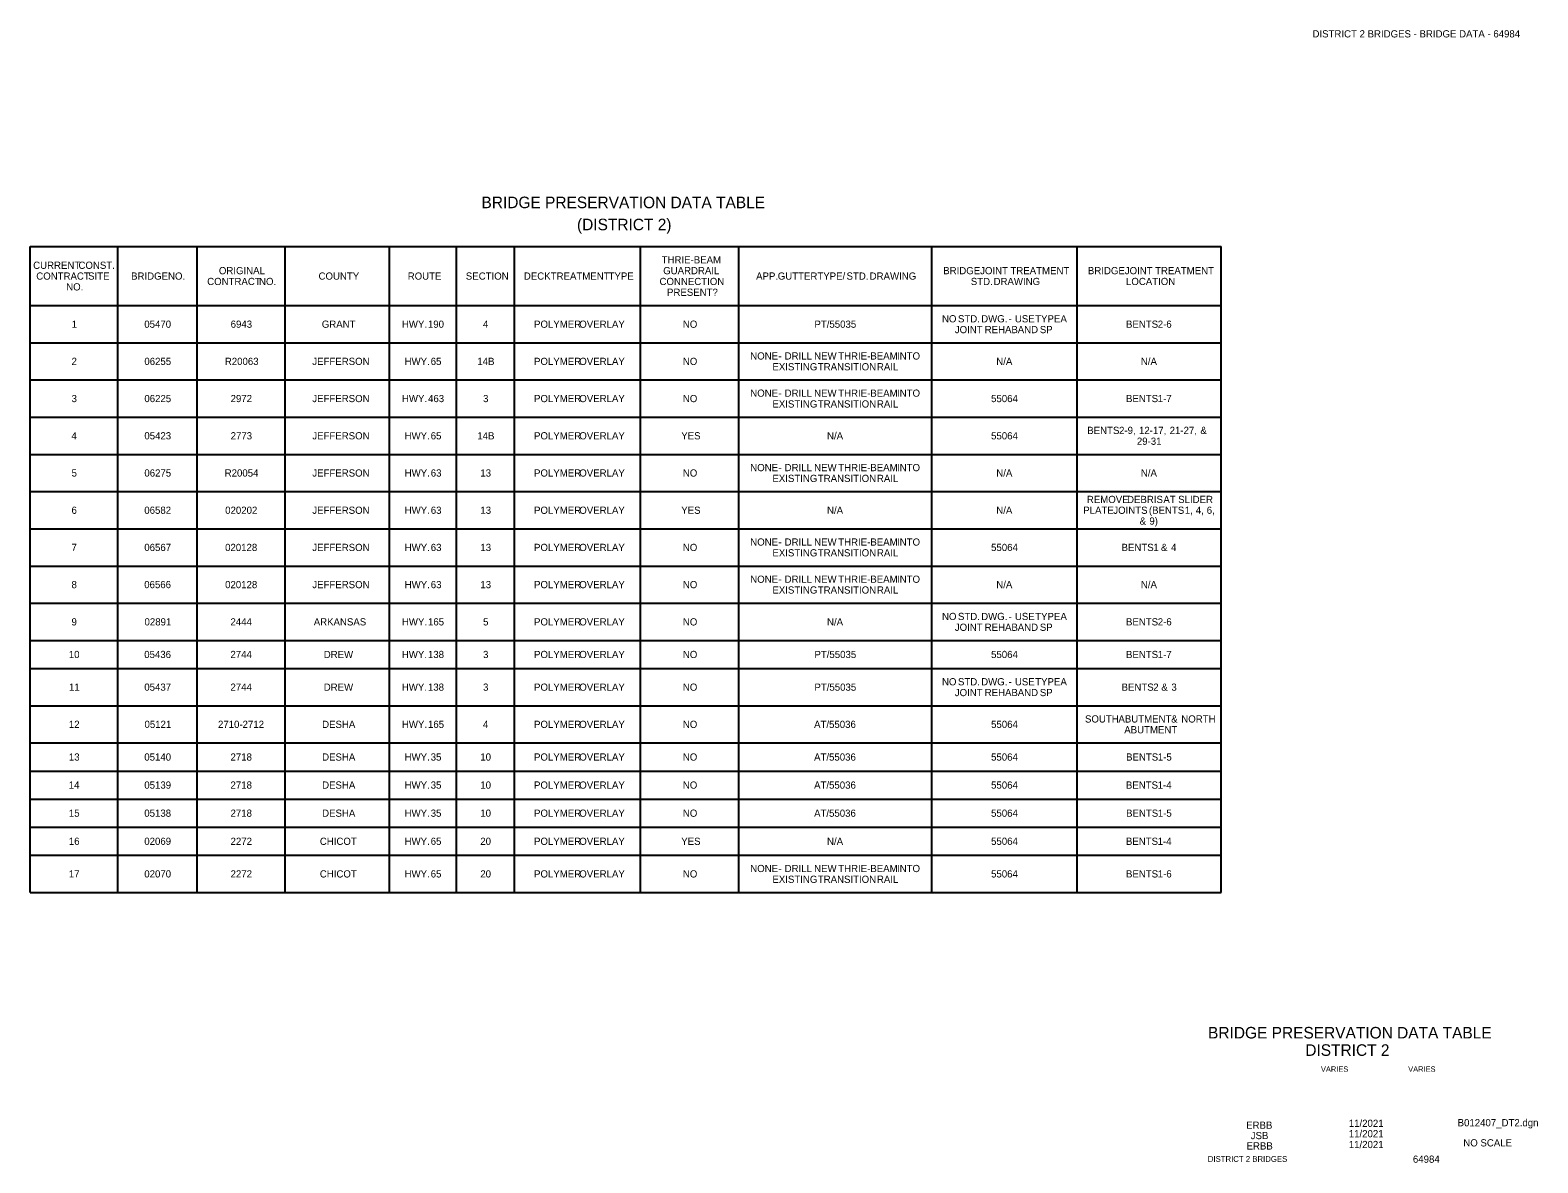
# Model space of a CAD drawing. Extents: x 16 to 1228740, y 11 to 152440.
import ezdxf

# ---------------------------------------------------------------- set-up
doc = ezdxf.new("R2010")
doc.units = 0
for name, color, linetype in [('B_border', 7, 'Continuous'), ('B_Concrete hidden', 7, 'Continuous'), ('Default', 7, 'Continuous')]:
    doc.layers.add(name, color=color, linetype=linetype)

msp = doc.modelspace()

# ---------------------------------------------------------------- linework, layer by layer
at = {"layer": 'B_border'}
msp.add_line((16.2529, 12.0926), (16.2529, 12.0926), dxfattribs=at)
at = {"layer": 'Default'}
for p, q in [((16.2529, 12.0926), (17.9726, 12.0926)), ((16.2529, 11.1597), (16.2529, 12.0926)), ((16.3796, 11.1597), (16.3796, 12.0926)), ((16.4942, 11.1597), (16.4942, 12.0926)), ((16.6209, 11.1597), (16.6209, 12.0926)), ((16.772, 11.1597), (16.772, 12.0926)), ((16.8684, 11.1597), (16.8684, 12.0926)), ((16.9525, 11.1597), (16.9525, 12.0926)), ((17.134, 11.1597), (17.134, 12.0926)), ((17.276, 11.1597), (17.276, 12.0926)), ((17.5548, 11.1597), (17.5548, 12.0926)), ((17.7647, 11.1597), (17.7647, 12.0926)), ((17.9726, 11.1597), (17.9726, 12.0926)), ((16.2529, 12.0074), (17.9726, 12.0074)), ((16.2529, 11.9537), (17.9726, 11.9537)), ((16.2529, 11.8999), (17.9726, 11.8999)), ((16.2529, 11.8462), (17.9726, 11.8462)), ((16.2529, 11.7924), (17.9726, 11.7924)), ((16.2529, 11.7387), (17.9726, 11.7387)), ((16.2529, 11.685), (17.9726, 11.685)), ((16.2529, 11.6312), (17.9726, 11.6312)), ((16.2529, 11.5775), (17.9726, 11.5775)), ((16.2529, 11.5237), (17.9726, 11.5237)), ((16.2529, 11.4832), (17.9726, 11.4832)), ((16.2529, 11.4294), (17.9726, 11.4294)), ((16.2529, 11.3757), (17.9726, 11.3757)), ((16.2529, 11.3351), (17.9726, 11.3351)), ((16.2529, 11.2946), (17.9726, 11.2946)), ((16.2529, 11.254), (17.9726, 11.254)), ((16.2529, 11.2135), (17.9726, 11.2135)), ((16.2529, 11.1597), (17.9726, 11.1597))]:
    msp.add_line(p, q, dxfattribs=at)

# ---------------------------------------------------------------- texts
at = {"layer": 'B_border'}
for s, p in [('BRIDGE PRESERVATION DATA TABLE ', (16.9046, 12.148)), ('(DISTRICT 2)', (17.0425, 12.1161))]:
    msp.add_text(s, height=0.0167, rotation=360, dxfattribs=at).set_placement(p)
at = {"layer": 'B_Concrete hidden'}
for s, height, p in [('DISTRICT 2 BRIDGES - BRIDGE DATA - 64984', 0.0104, (18.1046, 12.3946)), ('BRIDGE PRESERVATION DATA TABLE', 0.0167, (17.9538, 10.9489)), ('DISTRICT 2', 0.0167, (18.0942, 10.9238)), ('VARIES', 0.0078, (18.1168, 10.9008)), ('VARIES', 0.0078, (18.2428, 10.9008)), ('ERBB', 0.0104, (18.0088, 10.8185)), ('11/2021', 0.0104, (18.157, 10.8212)), ('B012407_DT2.dgn', 0.0104, (18.3142, 10.8221)), ('ERBB', 0.0104, (18.0094, 10.7885)), ('JSB', 0.0104, (18.0154, 10.8035)), ('11/2021', 0.0104, (18.157, 10.8062)), ('11/2021', 0.0104, (18.157, 10.7906)), ('NO SCALE', 0.0104, (18.3224, 10.793)), ('DISTRICT 2 BRIDGES', 0.0084, (17.9534, 10.7707)), ('64984', 0.01042, (18.2496, 10.7694))]:
    msp.add_text(s, height=height, dxfattribs=at).set_placement(p)
at = {"layer": 'Default'}
for s, p in [('CURRENT', (16.2572, 12.0604)), (' CONST.', (16.3188, 12.0604)), ('ORIGINAL', (16.5254, 12.0526)), ('THRIE-BEAM', (17.1648, 12.0682)), ('GUARDRAIL', (17.167, 12.0526)), ('BRIDGE', (17.5714, 12.0526)), (' JOINT', (17.6208, 12.0526)), (' TREATMENT', (17.6646, 12.0526)), ('BRIDGE', (17.7803, 12.0526)), (' JOINT', (17.8297, 12.0526)), (' TREATMENT', (17.8735, 12.0526)), ('CONTRACT', (16.2617, 12.0448)), ('NO.', (16.3049, 12.0292)), (' SITE', (16.3327, 12.0448)), ('BRIDGE', (16.3986, 12.0448)), (' NO.', (16.4481, 12.0448)), ('CONTRACT', (16.5085, 12.037)), (' NO.', (16.5795, 12.037)), ('COUNTY', (16.6693, 12.0448)), ('ROUTE', (16.7981, 12.0448)), ('SECTION', (16.882, 12.0448)), ('DECK', (16.9658, 12.0448)), (' TREATMENT', (17.0007, 12.0448)), (' TYPE', (17.0843, 12.0448)), ('CONNECTION', (17.1617, 12.037)), ('APP.', (17.3012, 12.0448)), (' GUTTER', (17.3286, 12.0448)), (' TYPE/', (17.3858, 12.0448)), (' STD.', (17.4279, 12.0448)), (' DRAWING', (17.4613, 12.0448)), ('STD.', (17.6112, 12.037)), (' DRAWING', (17.6402, 12.037)), ('LOCATION', (17.8353, 12.037)), ('PRESENT?', (17.1725, 12.0214)), ('1', (16.3129, 11.9753)), ('05470', (16.4177, 11.9753)), ('6943', (16.5424, 11.9753)), ('GRANT', (16.674, 11.9753)), ('HWY.', (16.7897, 11.9753)), (' 190', (16.8234, 11.9753)), ('4', (16.9067, 11.9753)), ('POLYMER', (16.9805, 11.9753)), (' OVERLAY', (17.042, 11.9753)), ('NO', (17.1954, 11.9753)), ('PT/55035', (17.3854, 11.9753)), ('NO', (17.5696, 11.9831)), ('JOINT', (17.5881, 11.9675)), (' STD.', (17.5888, 11.9831)), (' DWG.', (17.6223, 11.9831)), (' REHAB', (17.6274, 11.9675)), (' -', (17.6619, 11.9831)), (' USE', (17.671, 11.9831)), (' AND', (17.6751, 11.9675)), (' TYPE', (17.7003, 11.9831)), (' SP', (17.707, 11.9675)), (' A', (17.7368, 11.9831)), ('BENTS', (17.8353, 11.9753)), (' 2-6', (17.8773, 11.9753)), ('2', (16.3127, 11.9216)), ('06255', (16.4178, 11.9216)), ('R20063', (16.534, 11.9216)), ('JEFFERSON', (16.6603, 11.9216)), ('HWY.', (16.7936, 11.9216)), (' 65', (16.8274, 11.9216)), ('14B', (16.8986, 11.9216)), ('POLYMER', (16.9805, 11.9216)), (' OVERLAY', (17.042, 11.9216)), ('NO', (17.1954, 11.9216)), ('NONE', (17.2927, 11.9294)), (' -', (17.3295, 11.9294)), (' DRILL', (17.3385, 11.9294)), (' NEW', (17.3811, 11.9294)), (' THRIE-BEAM', (17.4159, 11.9294)), (' INTO', (17.5008, 11.9294)), ('N/A', (17.648, 11.9216)), ('N/A', (17.8568, 11.9216)), ('EXISTING', (17.3247, 11.9138)), (' TRANSITION', (17.3864, 11.9138)), (' RAIL', (17.4718, 11.9138)), ('3', (16.3127, 11.8679)), ('06225', (16.4178, 11.8679)), ('2972', (16.5423, 11.8679)), ('JEFFERSON', (16.6603, 11.8679)), ('HWY.', (16.7898, 11.8679)), (' 463', (16.8236, 11.8679)), ('3', (16.9069, 11.8679)), ('POLYMER', (16.9805, 11.8679)), (' OVERLAY', (17.042, 11.8679)), ('NO', (17.1954, 11.8679)), ('NONE', (17.2927, 11.8757)), ('EXISTING', (17.3247, 11.8601)), (' -', (17.3295, 11.8757)), (' DRILL', (17.3385, 11.8757)), (' NEW', (17.3811, 11.8757)), (' TRANSITION', (17.3864, 11.8601)), (' THRIE-BEAM', (17.4159, 11.8757)), (' RAIL', (17.4718, 11.8601)), (' INTO', (17.5008, 11.8757)), ('55064', (17.6405, 11.8679)), ('BENTS', (17.8353, 11.8679)), (' 1-7', (17.8773, 11.8679)), ('4', (16.3125, 11.8141)), ('05423', (16.4178, 11.8141)), ('2773', (16.5424, 11.8141)), ('JEFFERSON', (16.6603, 11.8141)), ('HWY.', (16.7936, 11.8141)), (' 65', (16.8274, 11.8141)), ('14B', (16.8986, 11.8141)), ('POLYMER', (16.9805, 11.8141)), (' OVERLAY', (17.042, 11.8141)), ('YES', (17.1931, 11.8141)), ('N/A', (17.4036, 11.8141)), ('55064', (17.6405, 11.8141)), ('BENTS', (17.7794, 11.8219)), (' 2-9,', (17.8214, 11.8219)), (' 12-17,', (17.8502, 11.8219)), (' 21-27,', (17.8945, 11.8219)), (' &', (17.9389, 11.8219)), ('29-31', (17.851, 11.8063)), ('NONE', (17.2927, 11.7682)), (' DRILL', (17.3385, 11.7682)), (' NEW', (17.3811, 11.7682)), (' THRIE-BEAM', (17.4159, 11.7682)), (' INTO', (17.5008, 11.7682)), ('5', (16.3127, 11.7604)), ('06275', (16.4178, 11.7604)), ('R20054', (16.5338, 11.7604)), ('JEFFERSON', (16.6603, 11.7604)), ('HWY.', (16.7937, 11.7604)), (' 63', (16.8275, 11.7604)), ('13', (16.903, 11.7604)), ('POLYMER', (16.9805, 11.7604)), (' OVERLAY', (17.042, 11.7604)), ('NO', (17.1954, 11.7604)), ('EXISTING', (17.3247, 11.7526)), (' -', (17.3295, 11.7682)), (' TRANSITION', (17.3864, 11.7526)), (' RAIL', (17.4718, 11.7526)), ('N/A', (17.648, 11.7604)), ('N/A', (17.8568, 11.7604)), ('6', (16.3126, 11.7066)), ('06582', (16.4177, 11.7066)), ('020202', (16.5345, 11.7066)), ('JEFFERSON', (16.6603, 11.7066)), ('HWY.', (16.7937, 11.7066)), (' 63', (16.8275, 11.7066)), ('13', (16.903, 11.7066)), ('POLYMER', (16.9805, 11.7066)), (' OVERLAY', (17.042, 11.7066)), ('YES', (17.1931, 11.7066)), ('N/A', (17.4036, 11.7066)), ('N/A', (17.648, 11.7066)), ('PLATE', (17.7736, 11.7066)), ('REMOVE', (17.7788, 11.7222)), (' JOINTS', (17.8131, 11.7066)), (' DEBRIS', (17.833, 11.7222)), (' (BENTS', (17.8645, 11.7066)), (' AT', (17.8854, 11.7222)), (' SLIDER', (17.9068, 11.7222)), (' 1,', (17.9164, 11.7066)), (' 4,', (17.9322, 11.7066)), (' 6,', (17.948, 11.7066)), ('&', (17.8551, 11.691)), (' 9)', (17.8652, 11.691)), ('NONE', (17.2927, 11.6607)), (' DRILL', (17.3385, 11.6607)), (' NEW', (17.3811, 11.6607)), (' THRIE-BEAM', (17.4159, 11.6607)), (' INTO', (17.5008, 11.6607)), ('7', (16.3126, 11.6529)), ('06567', (16.4177, 11.6529)), ('020128', (16.5344, 11.6529)), ('JEFFERSON', (16.6603, 11.6529)), ('HWY.', (16.7937, 11.6529)), (' 63', (16.8275, 11.6529)), ('13', (16.903, 11.6529)), ('POLYMER', (16.9805, 11.6529)), (' OVERLAY', (17.042, 11.6529)), ('NO', (17.1954, 11.6529)), ('EXISTING', (17.3247, 11.6451)), (' -', (17.3295, 11.6607)), (' TRANSITION', (17.3864, 11.6451)), (' RAIL', (17.4718, 11.6451)), ('55064', (17.6405, 11.6529)), ('BENTS', (17.8289, 11.6529)), (' 1', (17.8709, 11.6529)), (' &', (17.882, 11.6529)), (' 4', (17.8965, 11.6529)), ('8', (16.3126, 11.5992)), ('06566', (16.4176, 11.5992)), ('020128', (16.5344, 11.5992)), ('JEFFERSON', (16.6603, 11.5992)), ('HWY.', (16.7937, 11.5992)), (' 63', (16.8275, 11.5992)), ('13', (16.903, 11.5992)), ('POLYMER', (16.9805, 11.5992)), (' OVERLAY', (17.042, 11.5992)), ('NO', (17.1954, 11.5992)), ('NONE', (17.2927, 11.607)), (' -', (17.3295, 11.607)), (' DRILL', (17.3385, 11.607)), (' NEW', (17.3811, 11.607)), (' THRIE-BEAM', (17.4159, 11.607)), (' INTO', (17.5008, 11.607)), ('N/A', (17.648, 11.5992)), ('N/A', (17.8568, 11.5992)), ('EXISTING', (17.3247, 11.5914)), (' TRANSITION', (17.3864, 11.5914)), (' RAIL', (17.4718, 11.5914)), ('NO', (17.5696, 11.5532)), (' STD.', (17.5888, 11.5532)), (' DWG.', (17.6223, 11.5532)), (' USE', (17.671, 11.5532)), (' TYPE', (17.7003, 11.5532)), (' A', (17.7368, 11.5532)), ('9', (16.3126, 11.5454)), ('02891', (16.418, 11.5454)), ('2444', (16.5421, 11.5454)), ('ARKANSAS', (16.6624, 11.5454)), ('HWY.', (16.7897, 11.5454)), (' 165', (16.8235, 11.5454)), ('5', (16.9069, 11.5454)), ('POLYMER', (16.9805, 11.5454)), (' OVERLAY', (17.042, 11.5454)), ('NO', (17.1954, 11.5454)), ('N/A', (17.4036, 11.5454)), ('JOINT', (17.5881, 11.5376)), (' REHAB', (17.6274, 11.5376)), (' -', (17.6619, 11.5532)), (' AND', (17.6751, 11.5376)), (' SP', (17.707, 11.5376)), ('BENTS', (17.8353, 11.5454)), (' 2-6', (17.8773, 11.5454)), ('10', (16.3087, 11.4983)), ('05436', (16.4176, 11.4983)), ('2744', (16.5421, 11.4983)), ('DREW', (16.6768, 11.4983)), ('HWY.', (16.7896, 11.4983)), (' 138', (16.8234, 11.4983)), ('3', (16.9069, 11.4983)), ('POLYMER', (16.9805, 11.4983)), (' OVERLAY', (17.042, 11.4983)), ('NO', (17.1954, 11.4983)), ('PT/55035', (17.3854, 11.4983)), ('55064', (17.6405, 11.4983)), ('BENTS', (17.8353, 11.4983)), (' 1-7', (17.8773, 11.4983)), ('11', (16.309, 11.4511)), ('05437', (16.4177, 11.4511)), ('2744', (16.5421, 11.4511)), ('DREW', (16.6768, 11.4511)), ('HWY.', (16.7896, 11.4511)), (' 138', (16.8234, 11.4511)), ('3', (16.9069, 11.4511)), ('POLYMER', (16.9805, 11.4511)), (' OVERLAY', (17.042, 11.4511)), ('NO', (17.1954, 11.4511)), ('PT/55035', (17.3854, 11.4511)), ('NO', (17.5696, 11.4589)), ('JOINT', (17.5881, 11.4433)), (' STD.', (17.5888, 11.4589)), (' DWG.', (17.6223, 11.4589)), (' REHAB', (17.6274, 11.4433)), (' -', (17.6619, 11.4589)), (' USE', (17.671, 11.4589)), (' AND', (17.6751, 11.4433)), (' TYPE', (17.7003, 11.4589)), (' SP', (17.707, 11.4433)), (' A', (17.7368, 11.4589)), ('BENTS', (17.8289, 11.4511)), (' 2', (17.8708, 11.4511)), (' &', (17.8825, 11.4511)), (' 3', (17.897, 11.4511)), ('AT/55036', (17.3849, 11.3974)), ('SOUTH', (17.7761, 11.4052)), (' ABUTMENT', (17.8205, 11.4052)), (' &', (17.8967, 11.4052)), (' NORTH', (17.9113, 11.4052)), ('12', (16.3088, 11.3974)), ('05121', (16.418, 11.3974)), ('2710-2712', (16.5241, 11.3974)), ('DESHA', (16.6745, 11.3974)), ('HWY.', (16.7897, 11.3974)), (' 165', (16.8235, 11.3974)), ('4', (16.9067, 11.3974)), ('POLYMER', (16.9805, 11.3974)), (' OVERLAY', (17.042, 11.3974)), ('NO', (17.1954, 11.3974)), ('55064', (17.6405, 11.3974)), ('ABUTMENT', (17.8328, 11.3896)), ('13', (16.3088, 11.3502)), ('05140', (16.4177, 11.3502)), ('2718', (16.5422, 11.3502)), ('DESHA', (16.6745, 11.3502)), ('HWY.', (16.7936, 11.3502)), (' 35', (16.8274, 11.3502)), ('10', (16.9029, 11.3502)), ('POLYMER', (16.9805, 11.3502)), (' OVERLAY', (17.042, 11.3502)), ('NO', (17.1954, 11.3502)), ('AT/55036', (17.3849, 11.3502)), ('55064', (17.6405, 11.3502)), ('BENTS', (17.8354, 11.3502)), (' 1-5', (17.8774, 11.3502)), ('14', (16.3086, 11.3097)), ('05139', (16.4177, 11.3097)), ('2718', (16.5422, 11.3097)), ('DESHA', (16.6745, 11.3097)), ('HWY.', (16.7936, 11.3097)), (' 35', (16.8274, 11.3097)), ('10', (16.9029, 11.3097)), ('POLYMER', (16.9805, 11.3097)), (' OVERLAY', (17.042, 11.3097)), ('NO', (17.1954, 11.3097)), ('AT/55036', (17.3849, 11.3097)), ('55064', (17.6405, 11.3097)), ('BENTS', (17.8352, 11.3097)), (' 1-4', (17.8772, 11.3097)), ('15', (16.3088, 11.2691)), ('05138', (16.4177, 11.2691)), ('2718', (16.5422, 11.2691)), ('DESHA', (16.6745, 11.2691)), ('HWY.', (16.7936, 11.2691)), (' 35', (16.8274, 11.2691)), ('10', (16.9029, 11.2691)), ('POLYMER', (16.9805, 11.2691)), (' OVERLAY', (17.042, 11.2691)), ('NO', (17.1954, 11.2691)), ('AT/55036', (17.3849, 11.2691)), ('55064', (17.6405, 11.2691)), ('BENTS', (17.8354, 11.2691)), (' 1-5', (17.8774, 11.2691)), ('16', (16.3087, 11.2285)), ('02069', (16.4177, 11.2285)), ('2272', (16.5423, 11.2285)), ('CHICOT', (16.6712, 11.2285)), ('HWY.', (16.7936, 11.2285)), (' 65', (16.8274, 11.2285)), ('20', (16.9029, 11.2285)), ('POLYMER', (16.9805, 11.2285)), (' OVERLAY', (17.042, 11.2285)), ('YES', (17.1931, 11.2285)), ('N/A', (17.4036, 11.2285)), ('55064', (17.6405, 11.2285)), ('BENTS', (17.8352, 11.2285)), (' 1-4', (17.8772, 11.2285)), ('17', (16.3087, 11.1814)), ('02070', (16.4177, 11.1814)), ('2272', (16.5423, 11.1814)), ('CHICOT', (16.6712, 11.1814)), ('HWY.', (16.7936, 11.1814)), (' 65', (16.8274, 11.1814)), ('20', (16.9029, 11.1814)), ('POLYMER', (16.9805, 11.1814)), (' OVERLAY', (17.042, 11.1814)), ('NO', (17.1954, 11.1814)), ('NONE', (17.2927, 11.1892)), (' -', (17.3295, 11.1892)), (' DRILL', (17.3385, 11.1892)), (' NEW', (17.3811, 11.1892)), (' THRIE-BEAM', (17.4159, 11.1892)), (' INTO', (17.5008, 11.1892)), ('55064', (17.6405, 11.1814)), ('BENTS', (17.8353, 11.1814)), (' 1-6', (17.8773, 11.1814)), ('EXISTING', (17.3247, 11.1736)), (' TRANSITION', (17.3864, 11.1736)), (' RAIL', (17.4718, 11.1736))]:
    msp.add_text(s, height=0.0104, dxfattribs=at).set_placement(p)

doc.saveas('drawing.dxf')
